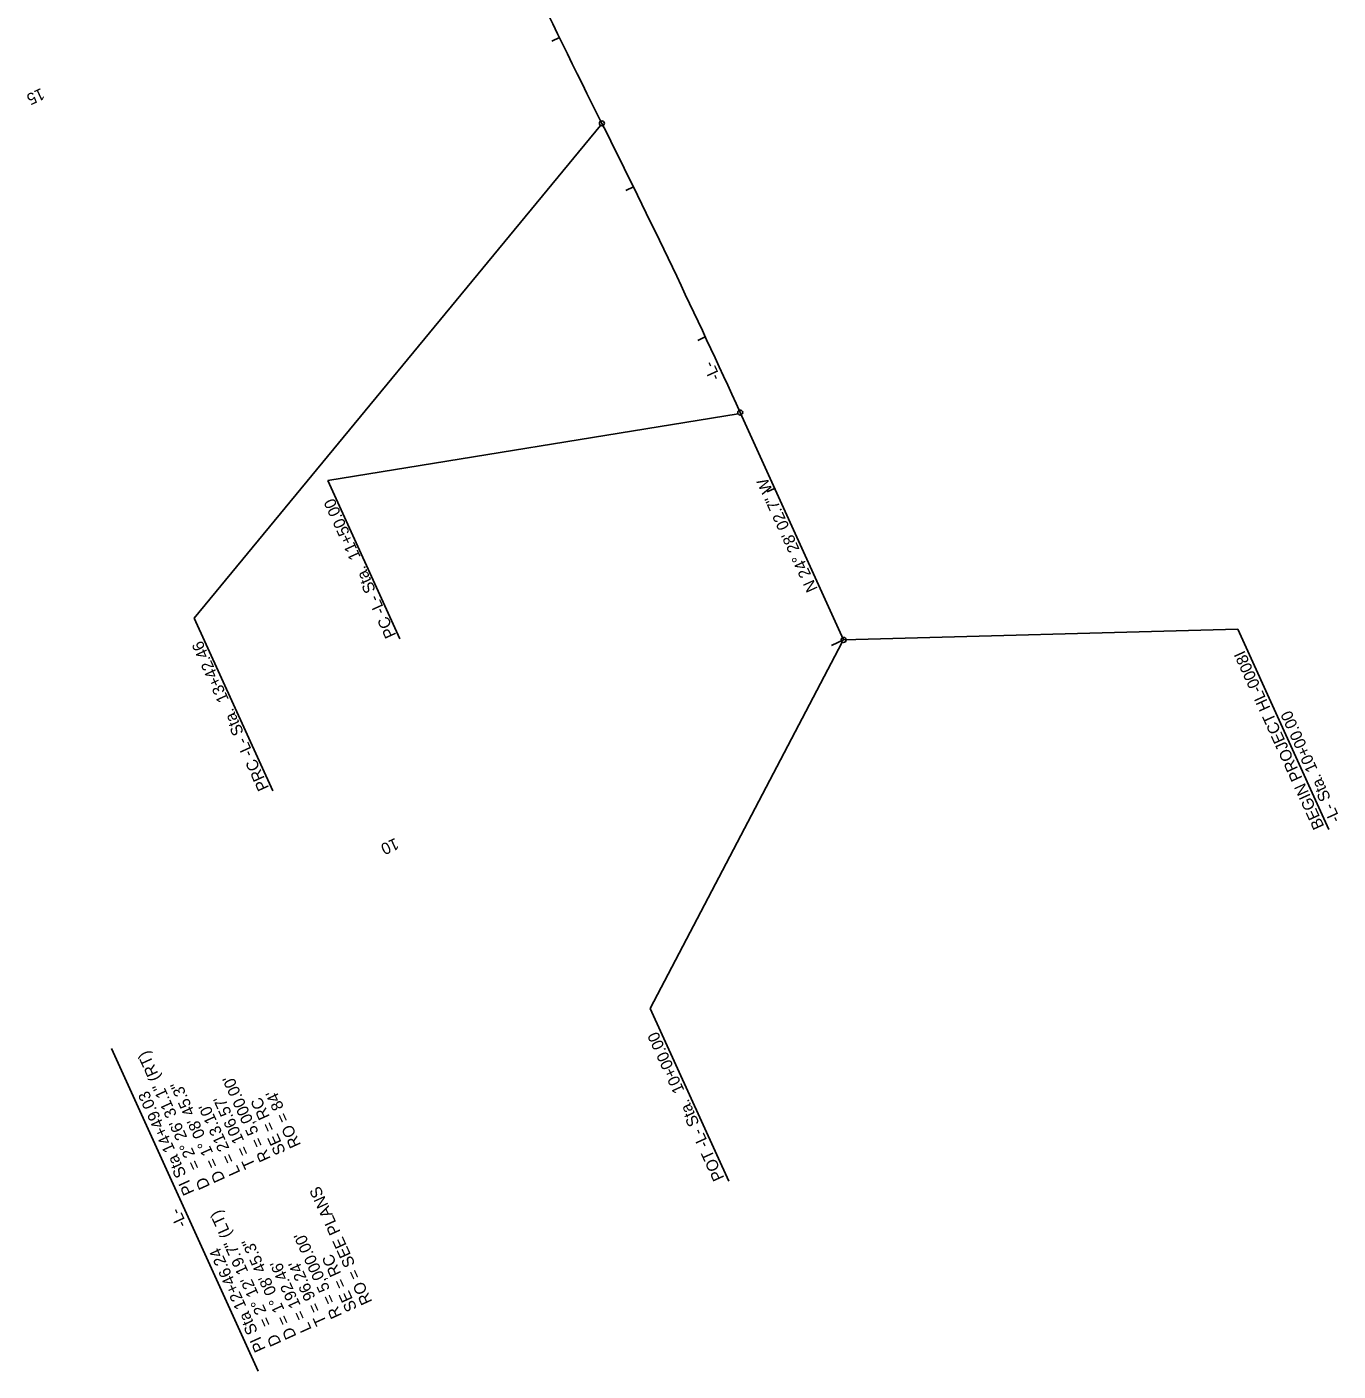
# Model space of a CAD drawing. Extents: x 2096901 to 2098386, y 684661 to 689731.
# Drawn here: x 2097598 to 2098386, y 684661 to 685468 of the extents above; entities that cross this region are included whole.
import ezdxf

# ---------------------------------------------------------------- set-up
doc = ezdxf.new("R2010")
doc.units = 0
for name, color, linetype in [('Prop Horizontal Alignment', 7, 'Continuous'), ('Prop Horizontal Alignment Curve and Spiral Data', 7, 'Continuous'), ('Prop Horizontal Alignment Direction Label', 7, 'Continuous'), ('Prop Horizontal Alignment Station Label', 7, 'Continuous'), ('Prop Horizontal Alignment Tick Label', 7, 'Continuous'), ('Prop Horizontal Alignment Tick Large', 7, 'Continuous'), ('Prop Horizontal Alignment Tick Small', 7, 'Continuous'), ('Scratch_Level_3', 7, 'Continuous'), ('Scratch_Level_5', 7, 'Continuous')]:
    doc.layers.add(name, color=color, linetype=linetype)

msp = doc.modelspace()

# ---------------------------------------------------------------- linework, layer by layer
at = {"layer": 'Prop Horizontal Alignment'}
msp.add_line((2098088.67, 685100.13), (2098026.55, 685236.66), dxfattribs=at)
for centre, start, end in [((2102411.4, 687654.74), 204.23092, 206.6729), ((2093475.56, 683165.78), 24.46742, 26.6729)]:
    msp.add_arc(centre, 5000, start, end, dxfattribs=at)
at = {"layer": 'Prop Horizontal Alignment Curve and Spiral Data'}
msp.add_line((2097737.13, 684661.22), (2097649, 684854.9), dxfattribs=at)
at = {"layer": 'Prop Horizontal Alignment Station Label'}
for p, q in [((2097942.63, 685409.02), (2097698.7, 685113.19)), ((2098025.29, 685235.84), (2097778.88, 685195.82)), ((2097778.88, 685195.82), (2097822.13, 685100.76)), ((2097698.65, 685113.28), (2097745.85, 685009.57)), ((2098325.39, 685106.57), (2098088.67, 685100.13)), ((2098325.39, 685106.57), (2098380.05, 684986.45)), ((2098087.86, 685098.87), (2097972.55, 684878.94)), ((2097972.55, 684878.94), (2098019.77, 684775.17))]:
    msp.add_line(p, q, dxfattribs=at)
for centre in [(2097943.48, 685410.26), (2098026.55, 685236.66), (2098088.67, 685100.13)]:
    msp.add_circle(centre, 1.5, dxfattribs=at)
at = {"layer": 'Prop Horizontal Alignment Tick Large'}
msp.add_line((2098088.67, 685100.13), (2098081.39, 685096.81), dxfattribs=at)
at = {"layer": 'Prop Horizontal Alignment Tick Small'}
for p, q in [((2097917.95, 685461.82), (2097913.46, 685459.63)), ((2097962.38, 685372.23), (2097957.9, 685370.03)), ((2098005.61, 685282.06), (2098001.08, 685279.95)), ((2098047.26, 685191.15), (2098042.7, 685189.08))]:
    msp.add_line(p, q, dxfattribs=at)
at = {"layer": 'Scratch_Level_3'}
msp.add_line((2098026.55, 685236.66), (2098088.67, 685100.13), dxfattribs=at)
at = {"layer": 'Scratch_Level_5'}
for centre, start, end in [((2102411.4, 687654.74), 204.23092, 206.6729), ((2093475.56, 683165.78), 24.46742, 26.6729)]:
    msp.add_arc(centre, 5000, start, end, dxfattribs=at)

# ---------------------------------------------------------------- texts
at = {"layer": 'Prop Horizontal Alignment Curve and Spiral Data'}
for s, p in [('= 2%%d 26\' 31.1" (RT)', (2097702.69, 684783.78)), ("R = 5,000.00'", (2097744.68, 684788.78)), ('PI Sta 14+49.03', (2097698.9, 684768.68)), ('D = 1%%d 08\' 45.3"', (2097717.38, 684776.35)), ("T = 106.57'", (2097735.58, 684784.63)), ('SE = RC', (2097753.79, 684792.92)), ("RO = 84'", (2097762.89, 684797.06)), ("L = 213.10'", (2097726.48, 684780.49)), ('D', (2097708.28, 684772.21)), ('RO = SEE PLANS', (2097805.73, 684702.9)), ('-L-', (2097694.44, 684749.25)), ('= 2%%d 12\' 19.7" (LT)', (2097745.53, 684689.62)), ("R = 5,000.00'", (2097787.53, 684694.62)), ('PI Sta 12+46.24', (2097741.74, 684674.52)), ('D = 1%%d 08\' 45.3"', (2097760.22, 684682.19)), ("L = 192.46'", (2097769.33, 684686.33)), ("T = 96.24'", (2097778.43, 684690.47)), ('SE = RC', (2097796.63, 684698.76)), ('D', (2097751.12, 684678.05))]:
    msp.add_text(s, height=7, rotation=114.46742, dxfattribs=at).set_placement(p)
at = {"layer": 'Prop Horizontal Alignment Direction Label'}
msp.add_text('N 24%%d 28\' 02.7" W', height=7, rotation=114.46742, dxfattribs=at).set_placement((2098073.19, 685130.75))
at = {"layer": 'Prop Horizontal Alignment Station Label'}
for s, p in [('-L-', (2098014.89, 685257.71)), ('PC -L- Sta.  11+50.00', (2097820.13, 685103.09)), ('PRC -L- Sta.  13+42.46', (2097743.7, 685011.42)), ('BEGIN PROJECT HL-0008I', (2098377.49, 684988.28)), ('-L- Sta. 10+00.00', (2098387.29, 684992.3)), ('POT -L- Sta.  10+00.00', (2098017.11, 684777.22))]:
    msp.add_text(s, height=7, rotation=114.46742, dxfattribs=at).set_placement(p)
at = {"layer": 'Prop Horizontal Alignment Tick Label'}
for s, rotation, p in [('15', 204.86767, (2097606.73, 685431.64)), ('10', 204.46742, (2097819.5, 684981.49))]:
    msp.add_text(s, height=7, rotation=rotation, dxfattribs=at).set_placement(p)

doc.saveas('drawing.dxf')
